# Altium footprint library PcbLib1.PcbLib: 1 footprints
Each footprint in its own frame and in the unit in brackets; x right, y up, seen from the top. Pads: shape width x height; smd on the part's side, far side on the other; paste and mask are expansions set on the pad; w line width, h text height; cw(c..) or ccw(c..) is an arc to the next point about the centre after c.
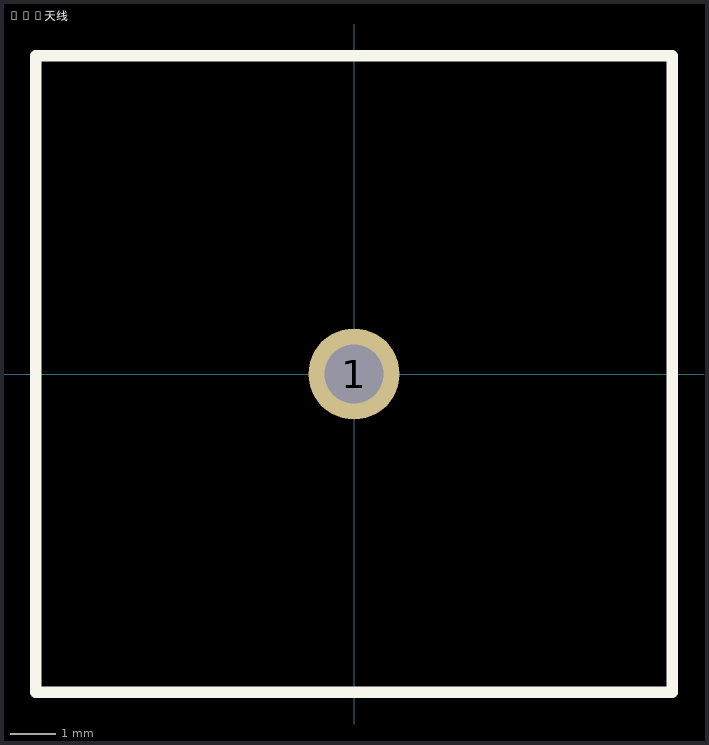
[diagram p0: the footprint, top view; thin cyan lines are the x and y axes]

## GPS天线 [mm]
pads (1):
  round 2 hole 1.3: 1(0,0)
Top Overlay:
  lines w0.254: -6.985,-6.985 6.985,-6.985 6.985,6.985 -6.985,6.985 -6.985,-6.985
